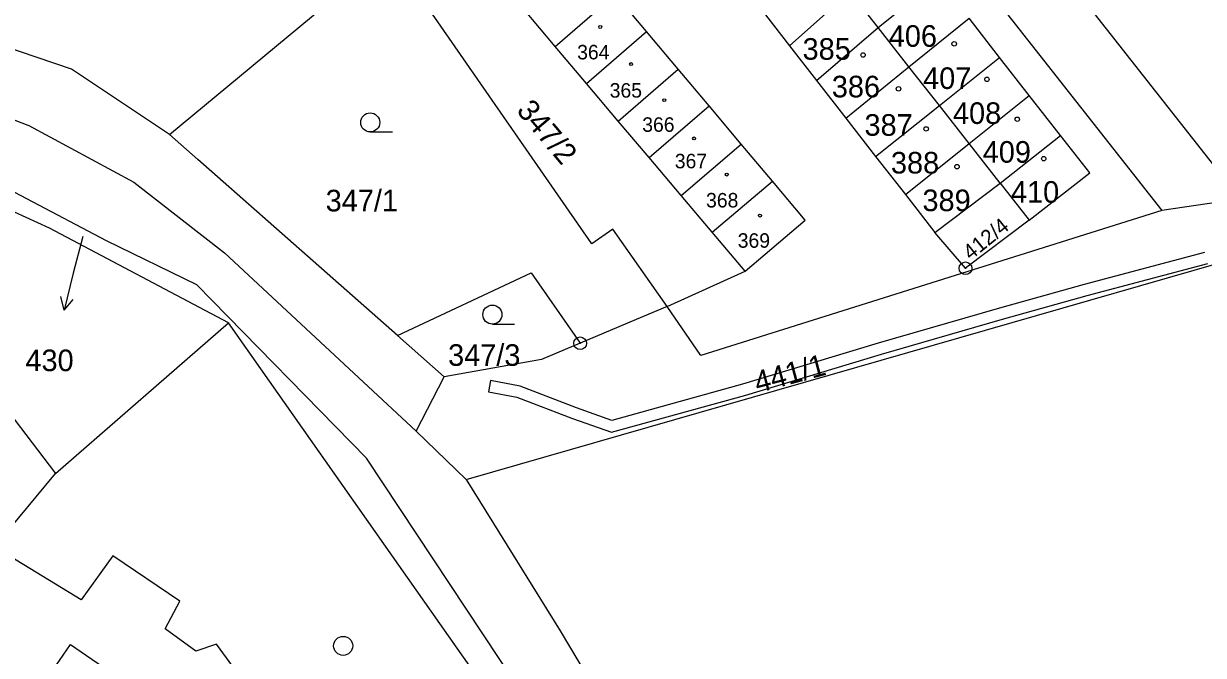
# Model space of a CAD drawing. Extents: x -504988 to -494607, y -1123820 to -1114018.
# Drawn here: x -496947.4 to -496854.6, y -1120483.5 to -1120433.8 of the extents above; entities that cross this region are included whole.
import ezdxf

# ---------------------------------------------------------------- set-up
doc = ezdxf.new("R2010")
doc.units = 0
for name, color, linetype in [('Hranice parcel', 7, 'Continuous'), ('Parcelní čísla', 7, 'Continuous'), ('Pop  PČ popisy', 7, 'Continuous'), ('Vnitřní kresba', 7, 'Continuous'), ('Věcná břemena k části', 7, 'Continuous'), ('Značky bodu BP', 7, 'Continuous'), ('Značky budov', 7, 'Continuous'), ('Značky kultur', 7, 'Continuous')]:
    doc.layers.add(name, color=color, linetype=linetype)

msp = doc.modelspace()

# ---------------------------------------------------------------- linework, layer by layer
at = {"layer": 'Hranice parcel'}
for p, q in [((-496851.74, -1120447.59), (-496877.69, -1120414.55)), ((-496935.95, -1120442.52), (-496918.66, -1120428.17)), ((-496880.22, -1120434.1), (-496875.47, -1120430.3)), ((-496905.61, -1120435.61), (-496900.89, -1120431.5)), ((-496898.42, -1120434.44), (-496900.89, -1120431.5)), ((-496887.19, -1120435.55), (-496882.42, -1120431.29)), ((-496880.22, -1120434.1), (-496882.42, -1120431.29)), ((-496889.71, -1120432.31), (-496887.19, -1120435.55)), ((-496905.61, -1120435.61), (-496908.09, -1120432.67)), ((-496877.8, -1120437.2), (-496873.06, -1120433.39)), ((-496870.67, -1120436.46), (-496873.06, -1120433.39)), ((-496885.05, -1120438.29), (-496880.22, -1120434.1)), ((-496877.8, -1120437.2), (-496880.22, -1120434.1)), ((-496903.14, -1120438.53), (-496898.42, -1120434.44)), ((-496895.93, -1120437.39), (-496898.42, -1120434.44)), ((-496903.14, -1120438.53), (-496905.61, -1120435.61)), ((-496887.19, -1120435.55), (-496885.05, -1120438.29)), ((-496875.39, -1120440.26), (-496870.67, -1120436.46)), ((-496868.33, -1120439.45), (-496870.67, -1120436.46)), ((-496900.65, -1120441.47), (-496895.93, -1120437.39)), ((-496893.51, -1120440.28), (-496895.93, -1120437.39)), ((-496882.74, -1120441.25), (-496877.8, -1120437.2)), ((-496875.39, -1120440.26), (-496877.8, -1120437.2)), ((-496900.65, -1120441.47), (-496903.14, -1120438.53)), ((-496885.05, -1120438.29), (-496882.74, -1120441.25)), ((-496873.05, -1120443.25), (-496868.33, -1120439.45)), ((-496865.86, -1120442.61), (-496868.33, -1120439.45)), ((-496898.23, -1120444.33), (-496893.51, -1120440.28)), ((-496890.98, -1120443.29), (-496893.51, -1120440.28)), ((-496880.41, -1120444.25), (-496875.39, -1120440.26)), ((-496873.05, -1120443.25), (-496875.39, -1120440.26)), ((-496898.23, -1120444.33), (-496900.65, -1120441.47)), ((-496882.74, -1120441.25), (-496880.41, -1120444.25)), ((-496870.62, -1120446.35), (-496865.86, -1120442.61)), ((-496895.7, -1120447.32), (-496890.98, -1120443.29)), ((-496888.53, -1120446.19), (-496890.98, -1120443.29)), ((-496878.07, -1120447.24), (-496873.05, -1120443.25)), ((-496870.62, -1120446.35), (-496873.05, -1120443.25)), ((-496895.7, -1120447.32), (-496898.23, -1120444.33)), ((-496880.41, -1120444.25), (-496878.07, -1120447.24)), ((-496893.26, -1120450.21), (-496888.53, -1120446.19)), ((-496875.74, -1120450.23), (-496870.62, -1120446.35)), ((-496870.62, -1120446.35), (-496868.33, -1120449.27)), ((-496893.26, -1120450.21), (-496895.7, -1120447.32)), ((-496878.07, -1120447.24), (-496875.74, -1120450.23)), ((-496851.74, -1120447.59), (-496857.89, -1120448.5)), ((-496890.67, -1120453.27), (-496893.26, -1120450.21)), ((-496918.01, -1120458.35), (-496907.5, -1120453.42)), ((-496907.5, -1120453.42), (-496904.06, -1120458.35)), ((-496896.81, -1120456.07), (-496890.67, -1120453.27)), ((-496944.92, -1120469.2), (-496931.3, -1120457.35)), ((-496910.28, -1120487.25), (-496931.3, -1120457.35)), ((-496914.34, -1120461.59), (-496918.01, -1120458.35)), ((-496904.06, -1120458.35), (-496903.65, -1120458.95)), ((-496916.54, -1120465.86), (-496914.34, -1120461.59)), ((-496916.54, -1120465.86), (-496912.61, -1120469.68)), ((-496949.37, -1120474.55), (-496944.92, -1120469.2))]:
    msp.add_line(p, q, dxfattribs=at)
for points in [[(-496913.41, -1120379.28), (-496886.68, -1120411.9), (-496857.89, -1120448.5)], [(-496935.95, -1120442.52), (-496943.66, -1120437.39), (-496972.17, -1120427.68), (-496983.4, -1120420.68), (-496983.74, -1120416.46), (-496981.47, -1120410.68), (-496975.37, -1120407.41)], [(-496896.81, -1120456.07), (-496901.09, -1120449.99), (-496902.73, -1120451.13), (-496918.66, -1120428.17)], [(-496966.36, -1120434.47), (-496947.02, -1120441.82), (-496938.75, -1120446.29), (-496931.62, -1120451.84), (-496916.54, -1120465.86)], [(-496918.01, -1120458.35), (-496933.72, -1120444.49), (-496935.95, -1120442.52)], [(-496868.33, -1120449.27), (-496863.57, -1120445.55), (-496865.86, -1120442.61)], [(-496931.3, -1120457.35), (-496945.39, -1120449.89), (-496949.06, -1120448.22), (-496953.48, -1120444.28)], [(-496870.25, -1120553.45), (-496896.08, -1120508.78), (-496908.69, -1120485.78), (-496920.45, -1120468), (-496933.79, -1120454.35), (-496940.92, -1120450.89), (-496953.48, -1120444.28)], [(-496890.67, -1120453.27), (-496885.94, -1120449.27), (-496888.53, -1120446.19)], [(-496857.89, -1120448.5), (-496894.17, -1120459.91), (-496896.81, -1120456.07)], [(-496912.61, -1120469.68), (-496851.35, -1120452.04), (-496832.87, -1120449.5)], [(-496868.33, -1120449.27), (-496873.34, -1120453.05), (-496875.74, -1120450.23)], [(-496896.81, -1120456.07), (-496898.74, -1120456.88), (-496903.65, -1120458.95)], [(-496903.65, -1120458.95), (-496906.68, -1120460.23), (-496914.34, -1120461.59)], [(-496978.4, -1120472.66), (-496966.17, -1120483.13), (-496949.09, -1120463.73), (-496944.92, -1120469.2)], [(-496912.61, -1120469.68), (-496905.22, -1120481.57), (-496882.64, -1120519.48)], [(-496947.76, -1120504.11), (-496946.75, -1120503.07), (-496929.97, -1120485.74), (-496932.25, -1120482.63), (-496933.87, -1120483.18), (-496936.3, -1120481.41), (-496935.13, -1120479.23), (-496940.4, -1120475.68), (-496942.89, -1120479.14), (-496948.48, -1120475.73), (-496949.37, -1120474.55)]]:
    msp.add_lwpolyline(points, dxfattribs=at)
at = {"layer": 'Pop  PČ popisy'}
for p, q in [((-496942.78, -1120450.55), (-496943.52, -1120453.45)), ((-496943.52, -1120453.45), (-496944.246, -1120456.362)), ((-496944.246, -1120456.362), (-496944.49, -1120455.269)), ((-496944.246, -1120456.362), (-496943.518, -1120455.511))]:
    msp.add_line(p, q, dxfattribs=at)
at = {"layer": 'Vnitřní kresba'}
for p, q in [((-496950.21, -1120492.08), (-496943.74, -1120482.65)), ((-496943.74, -1120482.65), (-496937.46, -1120486.95))]:
    msp.add_line(p, q, dxfattribs=at)
at = {"layer": 'Věcná břemena k části'}
msp.add_lwpolyline([(-496854.54, -1120451.82), (-496864, -1120454.33), (-496870.67, -1120456.2), (-496880.21, -1120458.94), (-496890.88, -1120462.17), (-496901.15, -1120465.02), (-496903.93, -1120464.03), (-496908.38, -1120462.33), (-496910.7, -1120461.88), (-496910.87, -1120462.77), (-496908.62, -1120463.19), (-496904.25, -1120464.87), (-496901.19, -1120465.96), (-496890.62, -1120463.03), (-496879.95, -1120459.8), (-496870.43, -1120457.06), (-496863.76, -1120455.19), (-496854.28, -1120452.68)], dxfattribs=at)
at = {"layer": 'Značky bodu BP'}
for centre, radius in [((-496873.34, -1120453.05), 0.5), ((-496873.34, -1120453.05), 0.0303), ((-496903.65, -1120458.95), 0.5), ((-496903.65, -1120458.95), 0.0303)]:
    msp.add_circle(centre, radius, dxfattribs=at)
at = {"layer": 'Značky budov'}
for centre, radius in [((-496902.075, -1120434.069), 0.117), ((-496874.227, -1120435.399), 0.175), ((-496881.397, -1120436.279), 0.175), ((-496899.645, -1120436.989), 0.117), ((-496871.657, -1120438.189), 0.175), ((-496878.607, -1120438.939), 0.175), ((-496897.035, -1120439.829), 0.117), ((-496869.267, -1120441.329), 0.175), ((-496876.437, -1120442.089), 0.175), ((-496894.685, -1120442.839), 0.117), ((-496867.187, -1120444.429), 0.175), ((-496874.007, -1120445.059), 0.175), ((-496892.115, -1120445.679), 0.117), ((-496889.505, -1120448.909), 0.117)]:
    msp.add_circle(centre, radius, dxfattribs=at)
at = {"layer": 'Značky kultur'}
for p, q in [((-496920.163, -1120442.33), (-496918.413, -1120442.33)), ((-496910.553, -1120457.45), (-496908.803, -1120457.45))]:
    msp.add_line(p, q, dxfattribs=at)
for centre in [(-496920.163, -1120441.58), (-496910.553, -1120456.7), (-496922.293, -1120482.76)]:
    msp.add_circle(centre, 0.75, dxfattribs=at)

# ---------------------------------------------------------------- texts
at = {"layer": 'Parcelní čísla'}
for s, height, p in [('406', 1.7, (-496879.375, -1120435.63)), ('385', 1.7, (-496886.155, -1120436.65)), ('364', 1.139, (-496903.887, -1120436.619)), ('386', 1.7, (-496883.855, -1120439.61)), ('407', 1.7, (-496876.675, -1120438.95)), ('365', 1.139, (-496901.327, -1120439.629)), ('408', 1.7, (-496874.325, -1120441.7)), ('366', 1.139, (-496898.767, -1120442.319)), ('387', 1.7, (-496881.285, -1120442.63)), ('409', 1.7, (-496871.985, -1120444.75)), ('367', 1.139, (-496896.207, -1120445.189)), ('388', 1.7, (-496879.205, -1120445.6)), ('410', 1.7, (-496869.765, -1120447.9)), ('347/1', 1.7, (-496923.668, -1120448.58)), ('368', 1.139, (-496893.747, -1120448.269)), ('389', 1.7, (-496876.725, -1120448.56)), ('369', 1.139, (-496891.257, -1120451.439)), ('347/3', 1.7, (-496914.038, -1120460.73)), ('430', 1.7, (-496947.285, -1120461.148))]:
    msp.add_text(s, height=height, dxfattribs=at).set_placement(p)
for s, height, rotation, p in [('347/2', 1.7, 310, (-496908.721, -1120440.679)), ('412/4', 1.2, 39, (-496872.931, -1120452.461)), ('441/1', 1.7, 15, (-496889.696, -1120462.884))]:
    msp.add_text(s, height=height, rotation=rotation, dxfattribs=at).set_placement(p)

doc.saveas('drawing.dxf')
